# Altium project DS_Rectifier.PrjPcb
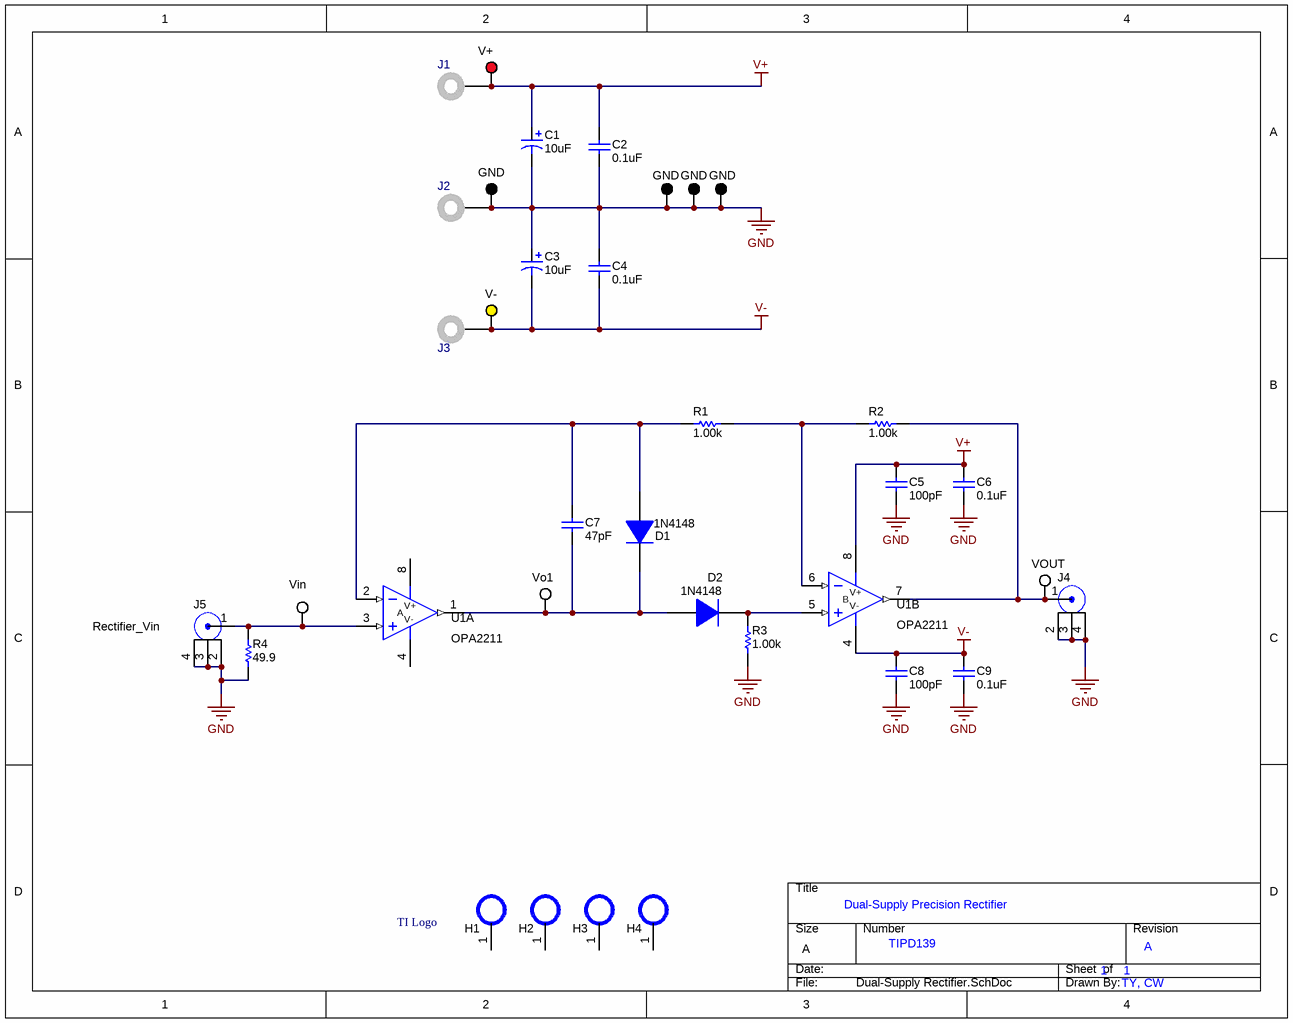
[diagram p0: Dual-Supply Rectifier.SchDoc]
CopyrightYear: 2012; PCB_Layout: TY; PCB_Rev: A; PRJ_Customer: TI Precision Designs; PRJ_Engineer: Ting Ye, Collin Wells; PRJ_Number: TIPD; PRJ_Title: Dual Supply Precision Rectifier; SCH_Rev: A; TechSupport: http://www.ti.com/support
1 sheet, 35 parts. Net scope: global (net labels, ports and power ports of the same name join across sheets).
Board file: Dual-Supply Rectifier2.PcbDoc

## Sheet Dual-Supply Rectifier.SchDoc: Main
size A; Date: Not shown in title block; ApprovedBy: Not shown in title block; CheckedBy: Not shown in title block; Author: Not shown in title block; CompanyName: Not shown in title block; DrawnBy: Not shown in title block; Engineer: Not shown in title block; Organization: Not shown in title block; Address1: Not shown in title block; Address2: Not shown in title block; Address3: Not shown in title block; Address4: Not shown in title block; DocumentNumber: 1; Revision: Use project parameter SCH_Rev; SheetNumber: 1; SheetTotal: 1; PageSetup: Record=PageOptions|CenterHorizontal=True|CenterVertical=True|PrintScale=0.70|XCorrection=1.00|YCorrection=1.00|PrintKind=0|BorderSize=5000000|LeftOffset=0|BottomOffset=0|Orientation=2|PaperLength=1000|PaperWidth=1000|Scale=100|PaperSource=15|PrintQuality=600|MediaType=1|DitherType=10|PaperKind=Letter|PrintScaleMode=1

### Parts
C1  ValueDisplayed: 10uF  [7343-43]  (hidden comment: TPSE106K050R0400)
C2  ValueDisplayed: 0.1uF  [0603]  (hidden comment: GRM188R72A104KA35D)
C3  ValueDisplayed: 10uF  [7343-43]  (hidden comment: TPSE106K050R0400)
C4  ValueDisplayed: 0.1uF  [0603]  (hidden comment: GRM188R72A104KA35D)
C5  ValueDisplayed: 100pF  [0603]  (hidden comment: C1608C0G1H101J)
C6  ValueDisplayed: 0.1uF  [0603]  (hidden comment: GRM188R72A104KA35D)
C7  ValueDisplayed: 47pF  [0603]  (hidden comment: 47P)
C8  ValueDisplayed: 100pF  [0603]  (hidden comment: C1608C0G1H101J)
C9  ValueDisplayed: 0.1uF  [0603]  (hidden comment: GRM188R72A104KA35D)
D1  1N4148  [SOD-123]
D2  1N4148  [SOD-123]
H1  NA  [Mounting Hole]  (value not drawn)  (no BOM)
H2  NA  [Mounting Hole]  (value not drawn)  (no BOM)
H3  NA  [Mounting Hole]  (value not drawn)  (no BOM)
H4  NA  [Mounting Hole]  (value not drawn)  (no BOM)
J1  V+  [Keystone_575-4]  (value not drawn)
J2  GND  [Keystone_575-4]  (value not drawn)
J3  V-  [Keystone_575-4]  (value not drawn)
J4  1-1634612-0  [Right Angle BNC]  (value not drawn)
J5  1-1634612-0  [Right Angle BNC]  (value not drawn)
R1  value 1.00k  [0603]  (hidden comment: 1KR)
R2  value 1.00k  [0603]  (hidden comment: 1KR)
R3  value 1.00k  [0603]  (hidden comment: 1kR)
R4  value 49.9  [0805]  (hidden comment: 49.9R)
TI1  Texas Instruments logo  [TI LOGO]  (value not drawn)  (no BOM)
TP1  V+  [Keystone5000]
TP2  GND  [Keystone5001]
TP3  GND  [Keystone5001]
TP4  GND  [Keystone5001]
TP5  GND  [Keystone5001]
TP6  V-  [Keystone5004]
TP7  Vo1  [Keystone5002]
TP8  VOUT  [Keystone5002]
TP9  Vin  [Keystone5002]
U1  OPA2211  [MRA08B_M]  (parts A,B of 2)

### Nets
GND: C1.2(-) C2.2 C3.1(+) C4.1 C5.2 C6.2 C8.2 C9.2 J2.1 J4.2 J4.3 J4.4 J5.2 J5.3 J5.4 R3.1 R4.1 TP2.1 TP3.1 TP4.1 TP5.1
V+: C1.1(+) C2.1 C5.1 C6.1 J1.1 TP1.1 U1.8(V+)
V-: C3.2(-) C4.2 C8.1 C9.1 J3.1 TP6.1 U1.4(V-)
NetC7_1: C7.1 D1.2(A) R1.2 U1.2(IN-)
NetC7_2: C7.2 D1.1(K) D2.2(A) TP7.1 U1.1(OUT)
NetD2_1: D2.1(K) R3.2 U1.5(IN+)
NetJ4_1: J4.1 R2.1 TP8.1 U1.7(OUT)
NetJ5_1: J5.1 R4.2 TP9.1 U1.3(IN+)
NetR1_1: R1.1 R2.2 U1.6(IN-)

Not connected (* = marked no-connect by the designer): H1 1; H2 1; H3 1; H4 1

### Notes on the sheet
- (near J5) Rectifier_Vin
- Dual-Supply Precision Rectifier
- TIPD139
- 1
- TY, CW
- A

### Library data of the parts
C1 C3 = TPSE106K050R0400: CAP, TANT, 10uF, 50V, +/-10%, 0.4 ohm, 7343-43 SMD; Manufacturer: AVX; Polarized: Y; CompType: Capacitor; U/M: EA; Cap_F: 0.00001; Tolerance_%: 10; Value1: 0.4 ohm; VDC_V: 50; ESR_Ohm: 0.4; IRMS_A: 0.578; TaMin_C: -55; TaMax_C: 125; Cap_Case: E
C2 C4 C6 C9 = GRM188R72A104KA35D: CAP, CERM, 0.1uF, 100V, +/-10%, X7R, 0603; Manufacturer: MuRata; Polarized: N; CompType: Capacitor; U/M: EA; Cap_F: 0.0000001; Tolerance_%: 10; VDC_V: 100; TaMin_C: -55; TaMax_C: 125
C5 C8 = C1608C0G1H101J: CAP, CERM, 100pF, 50V, +/-5%, C0G/NP0, 0603; Manufacturer: TDK; Polarized: N; CompType: Capacitor; U/M: EA; Cap_F: 0.0000000001; Tolerance_%: 5; ESR_Ohm: 0.1679; Value1: 0.1679 ohm; VDC_V: 50; TaMin_C: -55; TaMax_C: 125
C7 = C0603C470J5GACTU: CAP, CERM, 47pF, 50V, +/-5%, C0G/NP0, 0603; Manufacturer: Kemet; Polarized: N; CompType: Capacitor; U/M: EA; Cap_F: 0.000000000047; Tolerance_%: 5; Value1: Unknown; VDC_V: 50; TaMin_C: -55; TaMax_C: 125
D1 D2 = 1N4148W-7-F: Diode, Ultrafast, 100V, 0.15A, SOD-123; Manufacturer: Diodes Inc.; U/M: EA; Vf_V: 1.25; Io_A: 0.15; Vr_V: 100; TJmax_C: 150; Value: 1.25V
H1-H4 = Mounting Hole: Manufacturer: Used in BOM report; SymbolVersion: use current date i.e. 2008-05-20; SymbolCreator: Use LDAP id; CompType: Used in some BOM reports.  Useful for finding later.; U/M: EA, IN, or GM
J1-J3 = 575-4: Standard Banana Jack, Uninsulated, 5.5mm; Manufacturer: Keystone; CompType: Connector; U/M: EA
J4 J5 = BNC Right Angle: Right Angle BNC Connector; Manufacturer: TE Connectivity; SymbolVersion: use current date i.e. 2008-05-20; SymbolCreator: Use LDAP id; CompType: Used in some BOM reports.  Useful for finding later.; U/M: EA, IN, or GM
R1 R2 = RT0603BRD071KL: RES, 1.00k ohm, 0.1%, 0.1W, 0603; Manufacturer: Yageo America; CompType: Resistor; Res_ohm: 1000; Value_Code: 1k00; Tolerance_%: 0.1; VDC_V: 75; TempCo: 25 ppm/C; EIA_Code: E192; U/M: EA
R3 = RC0603FR-071KL: RES, 1.00k ohm, 1%, 0.1W, 0603; Manufacturer: Yageo America; CompType: Resistor; Res_ohm: 1000; Value_Code: 1k00; Tolerance_%: 1; Power_W: 0.1; VDC_V: 150; TempCo: 200 ppm/C; EIA_Code: E96; U/M: EA
R4 = CRCW080549R9FKEA: RES, 49.9 ohm, 1%, 0.125W, 0805; Manufacturer: Vishay-Dale; CompType: Resistor; Value_Code: 49R9; Tolerance_%: 1; Power_W: 0.125; VDC_V: 150; TempCo: 100 ppm/C; EIA_Code: E96; U/M: EA
TI1 = TI LOGO: TI BUG
TP1 = 5000: Test Point, TH, Miniature, Red; Manufacturer: Keystone; CompType: Test Point Loop; U/M: EA
TP2-TP5 = 5001: Test Point, TH, Miniature, Black; Manufacturer: Keystone; CompType: Test Point Loop; U/M: EA
TP6 = 5004: Test Point, TH, Miniature, Yellow; Manufacturer: Keystone; CompType: Test Point Loop; U/M: EA
TP7-TP9 = 5002: Test Point, TH, Miniature, White; Manufacturer: Keystone; CompType: Test Point Loop; U/M: EA
U1 = LF353M: IC OPAMP PRECISION DL LNLP 8SO; PartNumber: OPA2211AIDDA; Manufacturer: Texas Instruments Inc; CompType: OpAmp IC; TaMin_C: -40; TaMax_C: 125; PowerWise: N

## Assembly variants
001: all parts fitted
